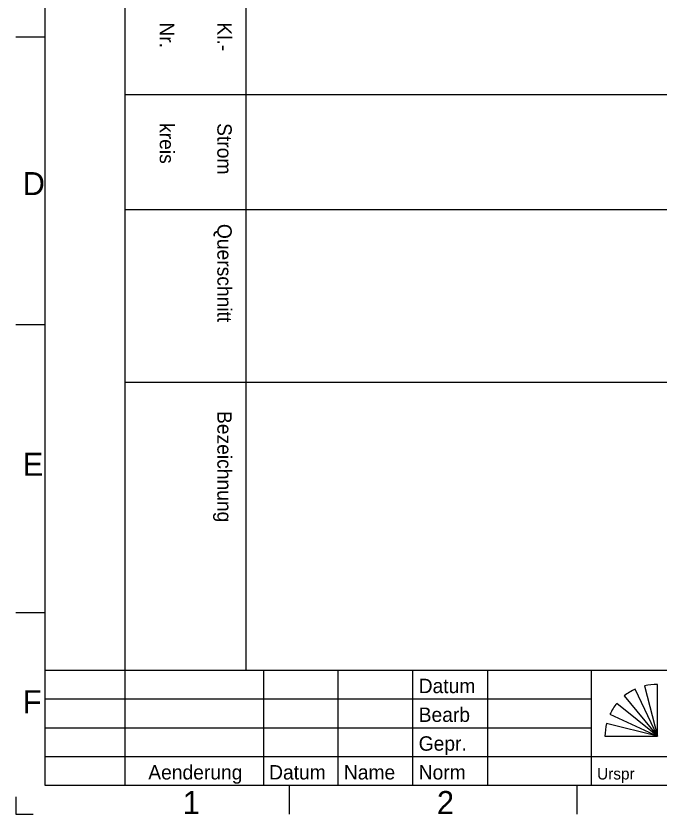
# Model space of a CAD drawing. Extents: x 0 to 395, y 0 to 270.
# Drawn here: x 0 to 111.8, y 0 to 138.6 of the extents above; entities that cross this region are included whole.
import ezdxf

# ---------------------------------------------------------------- set-up
doc = ezdxf.new("R2010")
doc.units = 0
for name, color, linetype in [('30_Graphik', 7, 'Continuous'), ('30_Text', 7, 'Continuous'), ('90_Plankopf', 7, 'Continuous')]:
    doc.layers.add(name, color=color, linetype=linetype)

msp = doc.modelspace()

# ---------------------------------------------------------------- linework, layer by layer
at = {"layer": '30_Graphik'}
for p, q in [((19, 25), (19, 265)), ((40, 25), (40, 265)), ((19, 125), (390, 125)), ((19, 105), (390, 105)), ((19, 75), (390, 75))]:
    msp.add_line(p, q, dxfattribs=at)
at = {"layer": '90_Plankopf'}
for p, q in [((5, 265), (5, 5)), ((0, 135), (5, 135)), ((0, 85), (5, 85)), ((0, 35), (5, 35)), ((5, 25), (390, 25)), ((19, 5), (19, 25)), ((43, 25), (43, 5)), ((56, 5), (56, 25)), ((69, 5), (69, 25)), ((82, 5), (82, 25)), ((100, 25), (100, 5)), ((109.27, 22.26), (111.48, 13.52)), ((111.48, 13.52), (111.48, 22.51)), ((111.48, 13.52), (107.63, 21.68)), ((5, 20), (100, 20)), ((105.74, 20.52), (111.48, 13.52)), ((111.48, 13.52), (104.43, 19.22)), ((103.24, 17.34), (111.48, 13.52)), ((111.48, 13.52), (102.66, 15.72)), ((5, 15), (100, 15)), ((102.36, 13.52), (111.48, 13.52)), ((5, 10), (100, 10)), ((100, 10), (225, 10)), ((5, 5), (390, 5)), ((47.5, 5), (47.5, 0)), ((97.5, 5), (97.5, 0)), ((0, 3), (0, 0)), ((0, 0), (3, 0))]:
    msp.add_line(p, q, dxfattribs=at)
for centre, start, end in [((111.45, 12.99), 89.8053, 103.1895), ((111.66, 13.05), 115.0126, 128.3968), ((111.82, 13.19), 140.7898, 154.174), ((111.89, 13.37), 165.7222, 179.1064)]:
    msp.add_arc(centre, 9.53, start, end, dxfattribs=at)

# ---------------------------------------------------------------- texts
at = {"layer": '30_Text'}
for s, p in [('Nr.', (25, 137.5)), ('Kl.-', (35, 137.5)), ('kreis', (25, 120)), ('Strom', (35, 120)), ('Querschnitt', (35, 102.5)), ('Bezeichnung', (35, 70))]:
    msp.add_text(s, height=2.5, rotation=270, dxfattribs=at).set_placement(p)
at = {"layer": '90_Plankopf'}
for s, height, p in [('D', 4, (1.17, 107.5)), ('E', 4, (1.17, 58.75)), ('Datum', 2.5, (70, 21)), ('F', 4, (1.17, 17.5)), ('Bearb', 2.5, (70, 16)), ('Gepr.', 2.5, (70, 11)), ('Aenderung', 2.5, (23, 6)), ('Datum', 2.5, (44, 6)), ('Name', 2.5, (57, 6)), ('Norm', 2.5, (70, 6)), ('Urspr', 2, (101, 6)), ('1', 4, (29, 0)), ('2', 4, (73.17, 0))]:
    msp.add_text(s, height=height, dxfattribs=at).set_placement(p)

doc.saveas('drawing.dxf')
